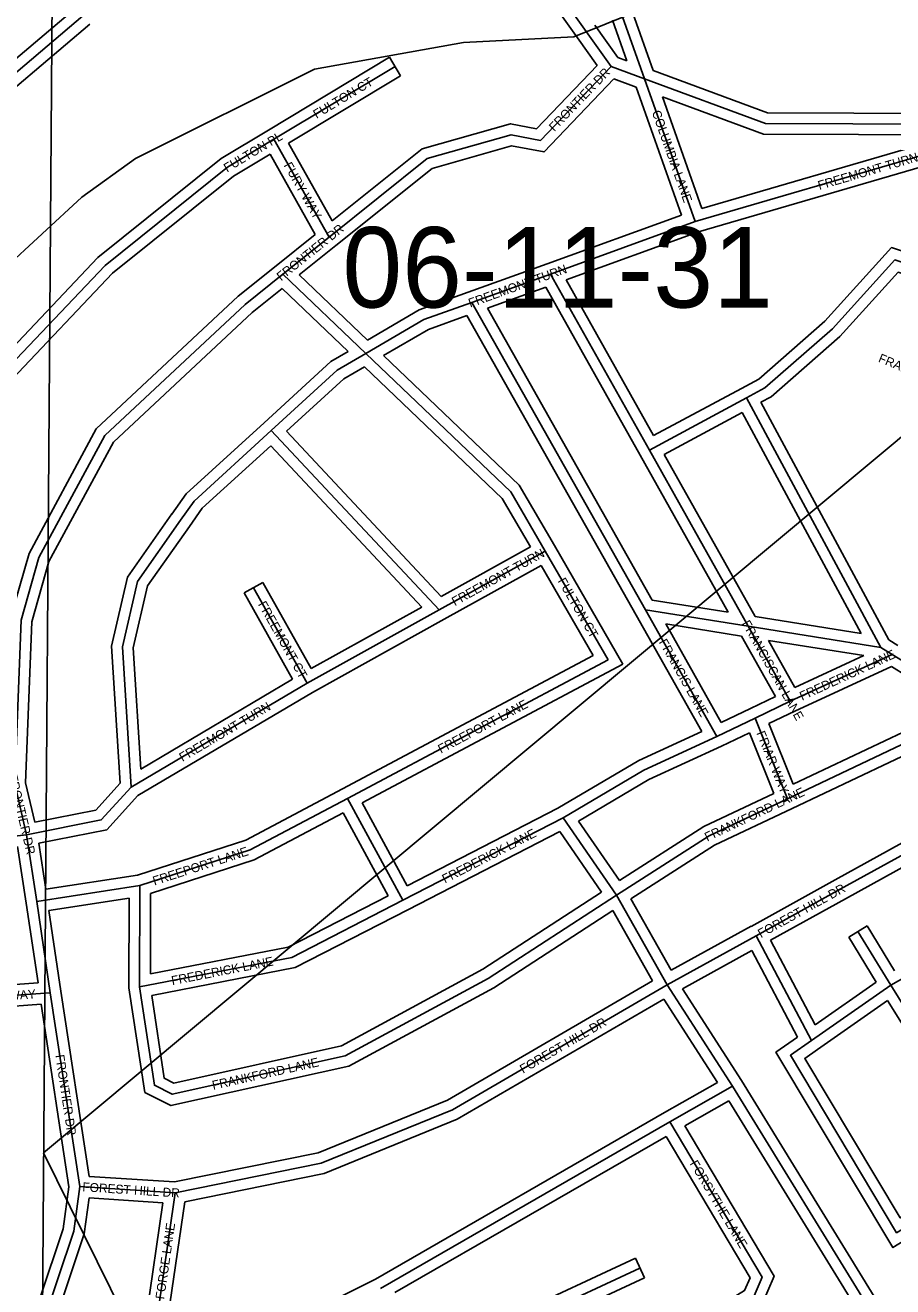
# Model space of a CAD drawing. Extents: x 457167 to 656239, y 1787309 to 1969297.
# Drawn here: x 585053 to 587479, y 1904923 to 1908451 of the extents above; entities that cross this region are included whole.
import ezdxf

# ---------------------------------------------------------------- set-up
doc = ezdxf.new("R2010")
doc.units = 0
for name, color, linetype in [('Level 1', 7, 'Continuous'), ('Level 2', 7, 'Continuous'), ('Level 31', 7, 'Continuous'), ('Level 32', 7, 'Continuous'), ('Level 34', 7, 'Continuous'), ('Level 5', 7, 'Continuous')]:
    doc.layers.add(name, color=color, linetype=linetype)

msp = doc.modelspace()

# ---------------------------------------------------------------- linework, layer by layer
at = {"layer": 'Level 1'}
for p, q in [((589240.382, 1908749.669), (585103.985, 1905297.891)), ((585128.849, 1908648.502), (585092.812, 1903792.198)), ((585103.985, 1905297.891), (587876.128, 1899689.718))]:
    msp.add_line(p, q, dxfattribs=at)
at = {"layer": 'Level 31'}
for p, q in [((586785.269, 1908300.911), (586723.609, 1908474.485)), ((586621.815, 1908433.221), (586691.245, 1908335.635)), ((585748.387, 1908131.598), (586087.176, 1908335.267)), ((586691.245, 1908335.635), (586785.269, 1908300.911)), ((586926.609, 1907901.368), (586785.269, 1908300.911)), ((586926.609, 1907901.368), (587856.559, 1908173.096)), ((585618.23, 1908053.663), (585748.387, 1908131.598)), ((585748.387, 1908131.598), (585902.352, 1907857.846)), ((585902.352, 1907857.846), (586176.77, 1908077.692)), ((586522.322, 1907754.853), (586926.609, 1907901.368)), ((585773.419, 1907754.453), (585902.352, 1907857.846)), ((585773.419, 1907754.453), (586005.681, 1907532.553)), ((586301.889, 1907675.631), (586522.322, 1907754.853)), ((586522.322, 1907754.853), (586798.586, 1907262.689)), ((586301.889, 1907675.631), (586787.579, 1906815.794)), ((586798.586, 1907262.689), (587070.004, 1907408.365)), ((587070.004, 1907408.365), (587446.029, 1906710.926)), ((585740.802, 1907317.054), (586210.312, 1906815.791)), ((586798.586, 1907262.689), (587075.174, 1906769.8)), ((586210.312, 1906815.791), (586506.884, 1906980.324)), ((586506.884, 1906980.324), (586683.054, 1906676.352)), ((585840.866, 1906611.035), (585691.334, 1906877.869)), ((585840.866, 1906611.035), (586210.312, 1906815.791)), ((586787.579, 1906815.794), (586987.184, 1906461.96)), ((586787.579, 1906815.794), (587075.174, 1906769.8)), ((587075.174, 1906769.8), (587192.718, 1906560.123)), ((587075.174, 1906769.8), (587446.029, 1906710.926)), ((587446.029, 1906710.926), (587477.463, 1906691.231)), ((585953.739, 1906288.633), (586683.054, 1906676.352)), ((587192.718, 1906560.123), (587477.463, 1906691.231)), ((587477.463, 1906691.231), (587719.41, 1906540.961)), ((585348.549, 1906319.97), (585840.866, 1906611.035)), ((587192.718, 1906560.123), (587094.086, 1906512.671)), ((587184.9, 1906287.77), (587719.41, 1906540.961)), ((587094.086, 1906512.671), (586987.184, 1906461.96)), ((587094.086, 1906512.671), (587184.9, 1906287.77)), ((586987.184, 1906461.96), (586782.609, 1906367.796)), ((586557.299, 1906234.763), (586782.609, 1906367.796)), ((585056.479, 1906187.074), (585023.373, 1906328.958)), ((587332.246, 1906034.4), (587841.063, 1906316.006)), ((585953.739, 1906288.633), (586108.965, 1906003.971)), ((586965.685, 1906184.177), (587184.9, 1906287.77)), ((586108.965, 1906003.971), (586557.299, 1906234.763)), ((586706.934, 1906017.751), (586557.299, 1906234.763)), ((584781.446, 1906154.15), (585056.479, 1906187.074)), ((585084.731, 1906000.471), (585056.479, 1906187.074)), ((586706.934, 1906017.751), (586965.685, 1906184.177)), ((585373.139, 1906045.01), (585084.731, 1906000.471)), ((585372.598, 1905761.37), (585373.139, 1906045.01)), ((587097.405, 1905904.655), (587332.246, 1906034.4)), ((587473.527, 1905766.497), (587974.083, 1906048.847)), ((585122.707, 1905745.122), (585084.731, 1906000.471)), ((586848.244, 1905767.301), (586706.934, 1906017.751)), ((586848.244, 1905767.301), (587097.405, 1905904.655)), ((587097.405, 1905904.655), (587251.671, 1905611.271)), ((587473.527, 1905766.497), (587381.935, 1905916.488)), ((584780.612, 1905720.69), (585122.707, 1905745.122)), ((585204.957, 1905203.138), (585122.707, 1905745.122)), ((587031.137, 1905483.681), (586848.244, 1905767.301)), ((587473.527, 1905766.497), (587251.671, 1905611.271)), ((587626.612, 1905520.027), (587473.527, 1905766.497)), ((586855.793, 1905384.008), (587031.137, 1905483.681)), ((587446.958, 1904807.623), (587031.137, 1905483.681)), ((586046.517, 1904918.255), (586855.793, 1905384.008)), ((585471.954, 1905185.899), (585204.957, 1905203.138)), ((585412.684, 1904777.642), (585471.954, 1905185.899)), ((586163.078, 1904692.94), (586772.06, 1904975.432))]:
    msp.add_line(p, q, dxfattribs=at)
for points in [[(586416.234, 1908812.524), (586439.84, 1908688.113), (586621.815, 1908433.221)], [(584695.28, 1907960.526), (584869.904, 1908185.283), (585213.439, 1908476.627)], [(586176.77, 1908077.692), (586411.799, 1908144.157), (586493.463, 1908128.731), (586691.245, 1908335.635)], [(586785.269, 1908300.911), (587123.245, 1908175.914), (587856.559, 1908173.096)], [(585023.373, 1906328.958), (584831.721, 1906345.692), (584756.782, 1906387.655), (584690.235, 1906496.149), (584707.408, 1906829.576), (584766.442, 1907112.738), (584991.883, 1907479.218), (585275.998, 1907779.041), (585618.23, 1908053.663)], [(587070.004, 1907408.365), (587121.552, 1907436.268), (587310.358, 1907602.101), (587484.908, 1907794.506), (587578.306, 1907764.151), (587630.71, 1907740.416), (587645.291, 1907545.478)], [(585023.373, 1906328.958), (585040.782, 1906787.477), (585091.024, 1906962.292), (585275.09, 1907303.762), (585667.407, 1907669.926), (585773.419, 1907754.453)], [(586005.681, 1907532.553), (586167.657, 1907627.521), (586301.889, 1907675.631)], [(585740.802, 1907317.054), (585925.489, 1907486.16), (586005.681, 1907532.553)], [(586005.681, 1907532.553), (586410.56, 1907145.963), (586506.884, 1906980.324)], [(585487.297, 1907066.626), (585524.908, 1907120.008), (585740.802, 1907317.054)], [(585348.549, 1906319.97), (585324.185, 1906712.022), (585366.177, 1906895.218), (585487.297, 1907066.626)], [(585056.479, 1906187.074), (585265.089, 1906228.492), (585348.549, 1906319.97)], [(585373.139, 1906045.01), (585681.676, 1906144.421), (585953.739, 1906288.633)], [(585372.598, 1905761.37), (585414.035, 1905486.377), (585463.895, 1905461.191), (585947.61, 1905568.634), (586347.922, 1905784.97), (586706.934, 1906017.751)], [(585372.598, 1905761.37), (585798.089, 1905844.196), (586108.965, 1906003.971)], [(585471.954, 1905185.899), (585880.286, 1905268.758), (586247.414, 1905418.246), (586848.244, 1905767.301)], [(587251.671, 1905611.271), (587192.786, 1905570.29), (587490.048, 1905074.092), (587789.524, 1905257.541)], [(586980.002, 1904825.586), (587088.527, 1904891.566), (587113.75, 1904950.065), (586855.793, 1905384.008)], [(585054.224, 1904678.329), (585188.188, 1905078.077), (585204.957, 1905203.138)]]:
    msp.add_lwpolyline(points, dxfattribs=at)
at = {"layer": 'Level 32'}
for p, q in [((586735.549, 1908351.253), (586695.34, 1908464.441)), ((586808.84, 1908324.18), (586751.879, 1908484.526)), ((586646.26, 1908450.613), (586710.324, 1908360.57)), ((586597.371, 1908415.829), (586652.429, 1908338.443)), ((585732.93, 1908157.311), (586071.719, 1908360.98)), ((586071.719, 1908360.98), (586102.634, 1908309.554)), ((586710.324, 1908360.57), (586735.549, 1908351.253)), ((585788.823, 1908120.901), (586102.634, 1908309.554)), ((586699.325, 1908300.669), (586761.679, 1908277.641)), ((586888.399, 1907919.429), (586761.679, 1908277.641)), ((586945.431, 1907938.121), (586834.9, 1908250.568)), ((585601.058, 1908078.346), (585732.975, 1908157.337)), ((586945.43, 1907938.121), (587649.641, 1908143.89)), ((585788.823, 1908120.901), (585911.176, 1907903.355)), ((586935.938, 1907872.837), (587830.477, 1908134.218)), ((585635.405, 1908028.978), (585737.352, 1908090.021)), ((585737.352, 1908090.021), (585863.726, 1907865.325)), ((585911.176, 1907903.354), (586162.757, 1908104.906)), ((585921.11, 1907834.431), (586190.784, 1908050.477)), ((586512.101, 1907783.059), (586888.399, 1907919.429)), ((585754.651, 1907777.858), (585863.725, 1907865.325)), ((586565.795, 1907738.696), (586935.938, 1907872.837)), ((585818.914, 1907752.479), (585921.121, 1907834.44)), ((586291.744, 1907703.863), (586512.176, 1907783.086)), ((585818.914, 1907752.479), (586010.037, 1907569.882)), ((586345.5, 1907659.424), (586508.586, 1907718.036)), ((586508.586, 1907718.036), (586772.426, 1907248.004)), ((586565.795, 1907738.697), (586810.337, 1907303.045)), ((585771.639, 1907714.663), (585956.037, 1907538.491)), ((586345.5, 1907659.424), (586806.592, 1906843.135)), ((586288.207, 1907638.856), (586761.459, 1906801.039)), ((586810.337, 1907303.045), (587055.817, 1907434.799)), ((586839.709, 1907250.711), (587057.809, 1907367.769)), ((587057.809, 1907367.769), (587390.848, 1906750.061)), ((587110.625, 1907396.238), (587468.675, 1906732.139)), ((585783.441, 1907315.417), (586216.215, 1906853.373)), ((585739.153, 1907274.93), (586162.105, 1906823.373)), ((586772.424, 1907248.007), (587018.653, 1906809.221)), ((586839.709, 1907250.711), (587094.227, 1906797.151)), ((586216.215, 1906853.374), (586465.56, 1906991.706)), ((586532.84, 1906995.367), (586724.616, 1906664.47)), ((586224.866, 1906789.556), (586495.692, 1906939.806)), ((586495.692, 1906939.806), (586641.494, 1906688.233)), ((585665.162, 1906863.203), (585717.505, 1906892.535)), ((585852.441, 1906651.748), (585717.505, 1906892.535)), ((585800.364, 1906621.941), (585665.162, 1906863.203)), ((586806.592, 1906843.135), (587018.652, 1906809.221)), ((585852.441, 1906651.748), (586162.105, 1906823.373)), ((586761.45, 1906801.054), (586945.049, 1906475.592)), ((585855.775, 1906584.996), (586224.854, 1906789.551)), ((586844.279, 1906776.344), (586999.58, 1906501.045)), ((586844.279, 1906776.344), (587056.104, 1906742.466)), ((587094.227, 1906797.151), (587390.847, 1906750.061)), ((587056.104, 1906742.467), (587150.932, 1906573.311)), ((587131.619, 1906730.462), (587398.814, 1906688.044)), ((587131.62, 1906730.461), (587205.338, 1906598.961)), ((587468.675, 1906732.139), (587493.392, 1906716.653)), ((585939.658, 1906315.123), (586641.494, 1906688.233)), ((585994.595, 1906276.375), (586724.615, 1906664.47)), ((587205.338, 1906598.961), (587398.814, 1906688.044)), ((587205.265, 1906532.871), (587475.349, 1906657.227)), ((587475.348, 1906657.228), (587656.83, 1906544.513)), ((585375.455, 1906370.727), (585800.365, 1906621.941)), ((585367.685, 1906296.431), (585855.775, 1906584.996)), ((587150.932, 1906573.311), (587081.079, 1906539.704)), ((587081.079, 1906539.704), (586999.58, 1906501.045)), ((587205.265, 1906532.871), (587132.434, 1906497.826)), ((587200.808, 1906328.5), (587656.83, 1906544.513)), ((587132.434, 1906497.826), (587200.808, 1906328.5)), ((587197.744, 1906260.656), (587720.625, 1906508.34)), ((586945.049, 1906475.592), (586768.675, 1906394.408)), ((587078.186, 1906471.921), (587000.042, 1906434.854)), ((587078.186, 1906471.922), (587146.479, 1906302.795)), ((587000.042, 1906434.854), (586796.546, 1906341.184)), ((586542.795, 1906261.038), (586768.676, 1906394.408)), ((587317.719, 1906060.648), (587826.839, 1906342.421)), ((585079.101, 1906222.151), (585053.505, 1906331.848)), ((586600.27, 1906225.294), (586796.545, 1906341.184)), ((585994.595, 1906276.375), (586121.281, 1906044.052)), ((586951.101, 1906210.466), (587146.48, 1906302.794)), ((587346.774, 1906008.151), (587828.174, 1906274.583)), ((585941.596, 1906248.241), (586067.909, 1906016.6)), ((586121.281, 1906044.052), (586542.796, 1906261.039)), ((586980.271, 1906157.888), (587197.718, 1906260.645)), ((586715.14, 1906058.699), (586600.27, 1906225.293)), ((586715.14, 1906058.699), (586951.1, 1906210.466)), ((586122.697, 1905977.296), (586547.576, 1906196.014)), ((586664.716, 1906026.131), (586547.577, 1906196.015)), ((585055.058, 1905996.058), (585031.171, 1906153.829)), ((585109.89, 1906034.712), (585090.433, 1906163.228)), ((586746.976, 1906007.834), (586980.272, 1906157.887)), ((585366.205, 1906074.295), (585109.889, 1906034.712)), ((587082.898, 1905930.914), (587317.739, 1906060.659)), ((585088.27, 1905772.739), (585055.058, 1905996.058)), ((585343.073, 1906010.009), (585118.795, 1905975.375)), ((585342.594, 1905759.151), (585343.073, 1906010.01)), ((585402.668, 1905797.786), (585403.098, 1906023.142)), ((586859.774, 1905807.915), (586746.975, 1906007.835)), ((587137.636, 1905892.606), (587346.754, 1906008.141)), ((585152.381, 1905749.535), (585118.794, 1905975.375)), ((586807.559, 1905778.36), (586696.485, 1905975.22)), ((586859.774, 1905807.915), (587082.922, 1905930.928)), ((587356.332, 1905900.852), (587407.539, 1905932.123)), ((587484.029, 1905806.865), (587407.539, 1905932.123)), ((587137.636, 1905892.606), (587262.375, 1905655.376)), ((587433.233, 1905774.919), (587356.332, 1905900.852)), ((586890.878, 1905756.544), (587085.093, 1905863.609)), ((587085.093, 1905863.609), (587212.788, 1905620.761)), ((584810.675, 1905752.913), (585088.27, 1905772.74)), ((585230.994, 1905231.52), (585152.381, 1905749.535)), ((587056.524, 1905499.671), (586890.878, 1905756.544)), ((587433.234, 1905774.919), (587262.376, 1905655.376)), ((584813.489, 1905692.961), (585097.204, 1905713.223)), ((585174.654, 1905202.875), (585097.204, 1905713.222)), ((586988.731, 1905494.085), (586838.551, 1905726.973)), ((587464.763, 1905723.749), (587268.87, 1905586.69)), ((587584.63, 1905530.76), (587464.763, 1905723.749)), ((587472.873, 1904822.754), (587056.524, 1905499.671)), ((586840.968, 1905410.09), (586988.731, 1905494.085)), ((586897.213, 1905373.042), (587020.768, 1905443.276)), ((587421.044, 1904792.491), (587020.767, 1905443.276)), ((586032.333, 1904944.705), (586840.829, 1905410.01)), ((586086.344, 1904906.561), (586845.121, 1905343.251)), ((585469.902, 1905216.094), (585230.994, 1905231.52)), ((585437.597, 1905158.053), (585230.97, 1905171.394)), ((585383.559, 1904785.834), (585437.597, 1905158.053)), ((585447.569, 1904809.122), (585498.61, 1905160.696)), ((586176.521, 1904732.246), (586759.436, 1905002.647)), ((586759.436, 1905002.647), (586784.684, 1904948.216)), ((586205.749, 1904679.661), (586784.684, 1904948.216))]:
    msp.add_line(p, q, dxfattribs=at)
for points in [[(586386.759, 1908806.931), (586411.594, 1908676.046), (586597.399, 1908415.789)], [(584689.11, 1908001.481), (584848.125, 1908206.15), (585172.241, 1908481.023)], [(584720.429, 1907943.995), (584891.684, 1908164.417), (585232.844, 1908453.746)], [(586162.757, 1908104.906), (586410.43, 1908174.947), (586483.029, 1908161.233), (586652.429, 1908338.444)], [(586808.84, 1908324.18), (587128.671, 1908205.894), (587852.314, 1908203.112)], [(586190.784, 1908050.476), (586413.169, 1908113.368), (586503.896, 1908096.229), (586699.324, 1908300.669)], [(586834.9, 1908250.569), (587117.82, 1908145.934), (587649.641, 1908143.89)], [(584999.099, 1906300.962), (584822.689, 1906316.366), (584735.299, 1906365.301), (584659.795, 1906488.397), (584677.566, 1906833.431), (584738.143, 1907123.993), (584967.963, 1907497.592), (585255.628, 1907801.161), (585601.058, 1908078.347)], [(584994.59, 1906361.586), (584840.754, 1906375.018), (584778.264, 1906410.009), (584720.674, 1906503.901), (584737.249, 1906825.72), (584794.741, 1907101.484), (585015.802, 1907460.845), (585296.369, 1907756.921), (585635.405, 1908028.977)], [(587055.817, 1907434.799), (587104.295, 1907461.041), (587289.282, 1907623.519), (587475.726, 1907829.036), (587589.164, 1907792.167), (587659.299, 1907760.402), (587672.995, 1907577.307)], [(584994.59, 1906361.586), (585010.941, 1906792.26), (585063.083, 1906973.684), (585251.019, 1907322.333), (585647.791, 1907692.656), (585754.716, 1907777.911)], [(587110.626, 1907396.238), (587138.809, 1907411.496), (587331.434, 1907580.683), (587494.089, 1907759.976), (587567.448, 1907736.134), (587602.121, 1907720.431), (587615.374, 1907543.241)], [(585053.505, 1906331.848), (585070.622, 1906782.695), (585118.964, 1906950.901), (585299.161, 1907285.191), (585687.024, 1907647.197), (585771.639, 1907714.662)], [(586010.037, 1907569.883), (586154.899, 1907654.818), (586291.768, 1907703.872)], [(586055.164, 1907526.786), (586180.415, 1907600.223), (586288.207, 1907638.856)], [(585720.543, 1907339.181), (585907.639, 1907510.492), (585956.037, 1907538.491)], [(586055.164, 1907526.786), (586434.355, 1907164.722), (586532.818, 1906995.406)], [(585783.44, 1907315.417), (585943.339, 1907461.828), (586001.234, 1907495.319)], [(586001.233, 1907495.319), (586386.765, 1907127.203), (586465.561, 1906991.706)], [(585462.773, 1907083.905), (585502.267, 1907139.962), (585720.579, 1907339.213)], [(585511.822, 1907049.346), (585547.549, 1907100.055), (585739.154, 1907274.93)], [(585317.819, 1906330.797), (585293.974, 1906714.494), (585338.258, 1906907.694), (585462.797, 1907083.939)], [(585375.454, 1906370.727), (585354.398, 1906709.551), (585394.096, 1906882.742), (585511.798, 1907049.311)], [(585079.101, 1906222.151), (585249.574, 1906255.998), (585317.819, 1906330.798)], [(585366.205, 1906074.295), (585669.961, 1906172.166), (585939.689, 1906315.141)], [(585090.433, 1906163.228), (585280.605, 1906200.986), (585367.685, 1906296.43)], [(585403.099, 1906023.142), (585693.392, 1906116.676), (585941.595, 1906248.241)], [(585406.547, 1905737.414), (585441.392, 1905506.169), (585467.854, 1905492.802), (585937.024, 1905597.015), (586332.605, 1905810.793), (586664.715, 1906026.131)], [(585402.668, 1905797.786), (585788.169, 1905872.829), (586067.909, 1906016.6)], [(585342.593, 1905759.151), (585386.679, 1905466.586), (585459.936, 1905429.579), (585958.195, 1905540.253), (586363.238, 1905759.146), (586696.485, 1905975.22)], [(585406.547, 1905737.414), (585808.009, 1905815.562), (586122.679, 1905977.288)], [(585469.903, 1905216.094), (585871.57, 1905297.602), (586234.158, 1905445.24), (586807.559, 1905778.36)], [(585498.61, 1905160.694), (585889.001, 1905239.914), (586260.671, 1905391.251), (586838.552, 1905726.973)], [(587212.787, 1905620.761), (587152.651, 1905578.908), (587479.884, 1905032.684), (587776.08, 1905214.121)], [(587268.809, 1905586.647), (587232.92, 1905561.671), (587500.213, 1905115.501), (587748.12, 1905267.36)], [(587019.887, 1904814.722), (587112.288, 1904870.901), (587147.358, 1904952.24), (586897.213, 1905373.043)], [(586964.418, 1904851.221), (587064.766, 1904912.23), (587080.142, 1904947.891), (586845.121, 1905343.251)], [(585027.364, 1904692.591), (585158.834, 1905084.899), (585174.654, 1905202.875)], [(585081.086, 1904664.066), (585217.541, 1905071.256), (585230.97, 1905171.395)], [(585447.569, 1904809.122), (585788.767, 1904823.346), (586032.333, 1904944.705)]]:
    msp.add_lwpolyline(points, dxfattribs=at)
at = {"layer": 'Level 5'}
msp.add_lwpolyline([(584607.396, 1904877.776), (584607.594, 1905052.841), (584516.06, 1905202.984), (584599.619, 1905369.648), (584591.378, 1905478.021), (584524.815, 1905594.793), (584499.973, 1905744.886), (584400.099, 1905903.37), (584333.635, 1906111.845), (584225.452, 1906295.378), (584233.89, 1906387.081), (584400.81, 1906586.956), (584442.589, 1906678.619), (584576.129, 1906820.213), (584618.234, 1907220.293), (584710.163, 1907445.269), (584877.142, 1907661.855), (585210.922, 1907969.944), (585361.073, 1908078.147), (585861.506, 1908327.716), (586278.41, 1908402.29), (586586.854, 1908418.631), (586853.746, 1908526.716)], dxfattribs=at)

# ---------------------------------------------------------------- texts
at = {"layer": 'Level 2'}
msp.add_text('06-11-31', height=225, dxfattribs=at).set_placement((585939.602, 1907661.286))
at = {"layer": 'Level 34'}
for s, height, rotation, p in [('FRONTIER DR', 25, 46.290244, (586532.834, 1908151.83)), ('FULTON CT', 25, 31.01225, (585867.456, 1908188.595)), ('COLUMBIA LANE', 25, 289.480972, (586804.923, 1908207.875)), ('FULTON PL', 25, 30.911653, (585617.176, 1908038.462)), ('FREEMONT TURN', 25, 16.287681, (587274.011, 1907989.856)), ('FURY WAY', 25, 299.354161, (585774.873, 1908059.009)), ('FRONTIER DR', 25, 38.725606, (585768.304, 1907734.331)), ('FREEMONT TURN', 25, 19.767372, (586297.625, 1907660.816)), ('FRANKFORD', 25, 337.6125, (587436.877, 1907510.054)), ('FREEMONT TURN', 25, 29.020147, (586254.357, 1906825.933)), ('FULTON CT', 25, 300.09455, (586541.039, 1906896.464)), ('FREEMONT CT', 25, 299.265719, (585702.999, 1906831.484)), ('FRANCISCAN LANE', 25, 299.274292, (587056.277, 1906777.947)), ('FRANCIS LANE', 25, 299.42775, (586824.034, 1906725.731)), ('FREDERICK LANE', 25, 24.722561, (587225.738, 1906561.566)), ('FREEMONT TURN', 25, 30.591486, (585492.485, 1906390.546)), ('FREEPORT LANE', 25, 27.995383, (586215.386, 1906413.575)), ('FRIAR WAY', 25, 291.988225, (587097.3, 1906471.326)), ('FRONTIER DR', 25, 283.133275, (585005.209, 1906351.793)), ('FRANKFORD LANE', 24.99916, 25.292864, (586960.182, 1906167.754)), ('FREDERICK LANE', 25, 27.237814, (586226.699, 1906050.519)), ('FREEPORT LANE', 25, 17.858592, (585413.875, 1906045.003)), ('FOREST HILL DR', 25, 28.919261, (587110.459, 1905897.587)), ('FREDERICK LANE', 25, 11.014889, (585463.913, 1905766.412)), ('FUCHSIA WAY', 25, 4.08475, (584851.232, 1905713.203)), ('FOREST HILL DR', 25, 30.154014, (586445.036, 1905518.601)), ('FRONTIER DR', 25, 278.628608, (585136.589, 1905570.344)), ('FRANKFORD LANE', 25, 12.522836, (585578.404, 1905473.822)), ('FORSYTHE LANE', 25, 300.72885, (586910.537, 1905267.456)), ('FOREST HILL DR', 25, 356.305472, (585211.77, 1905190.172)), ('FORGE LANE', 25, 81.738711, (585441.18, 1904886.934))]:
    msp.add_text(s, height=height, rotation=rotation, dxfattribs=at).set_placement(p)

doc.saveas('drawing.dxf')
